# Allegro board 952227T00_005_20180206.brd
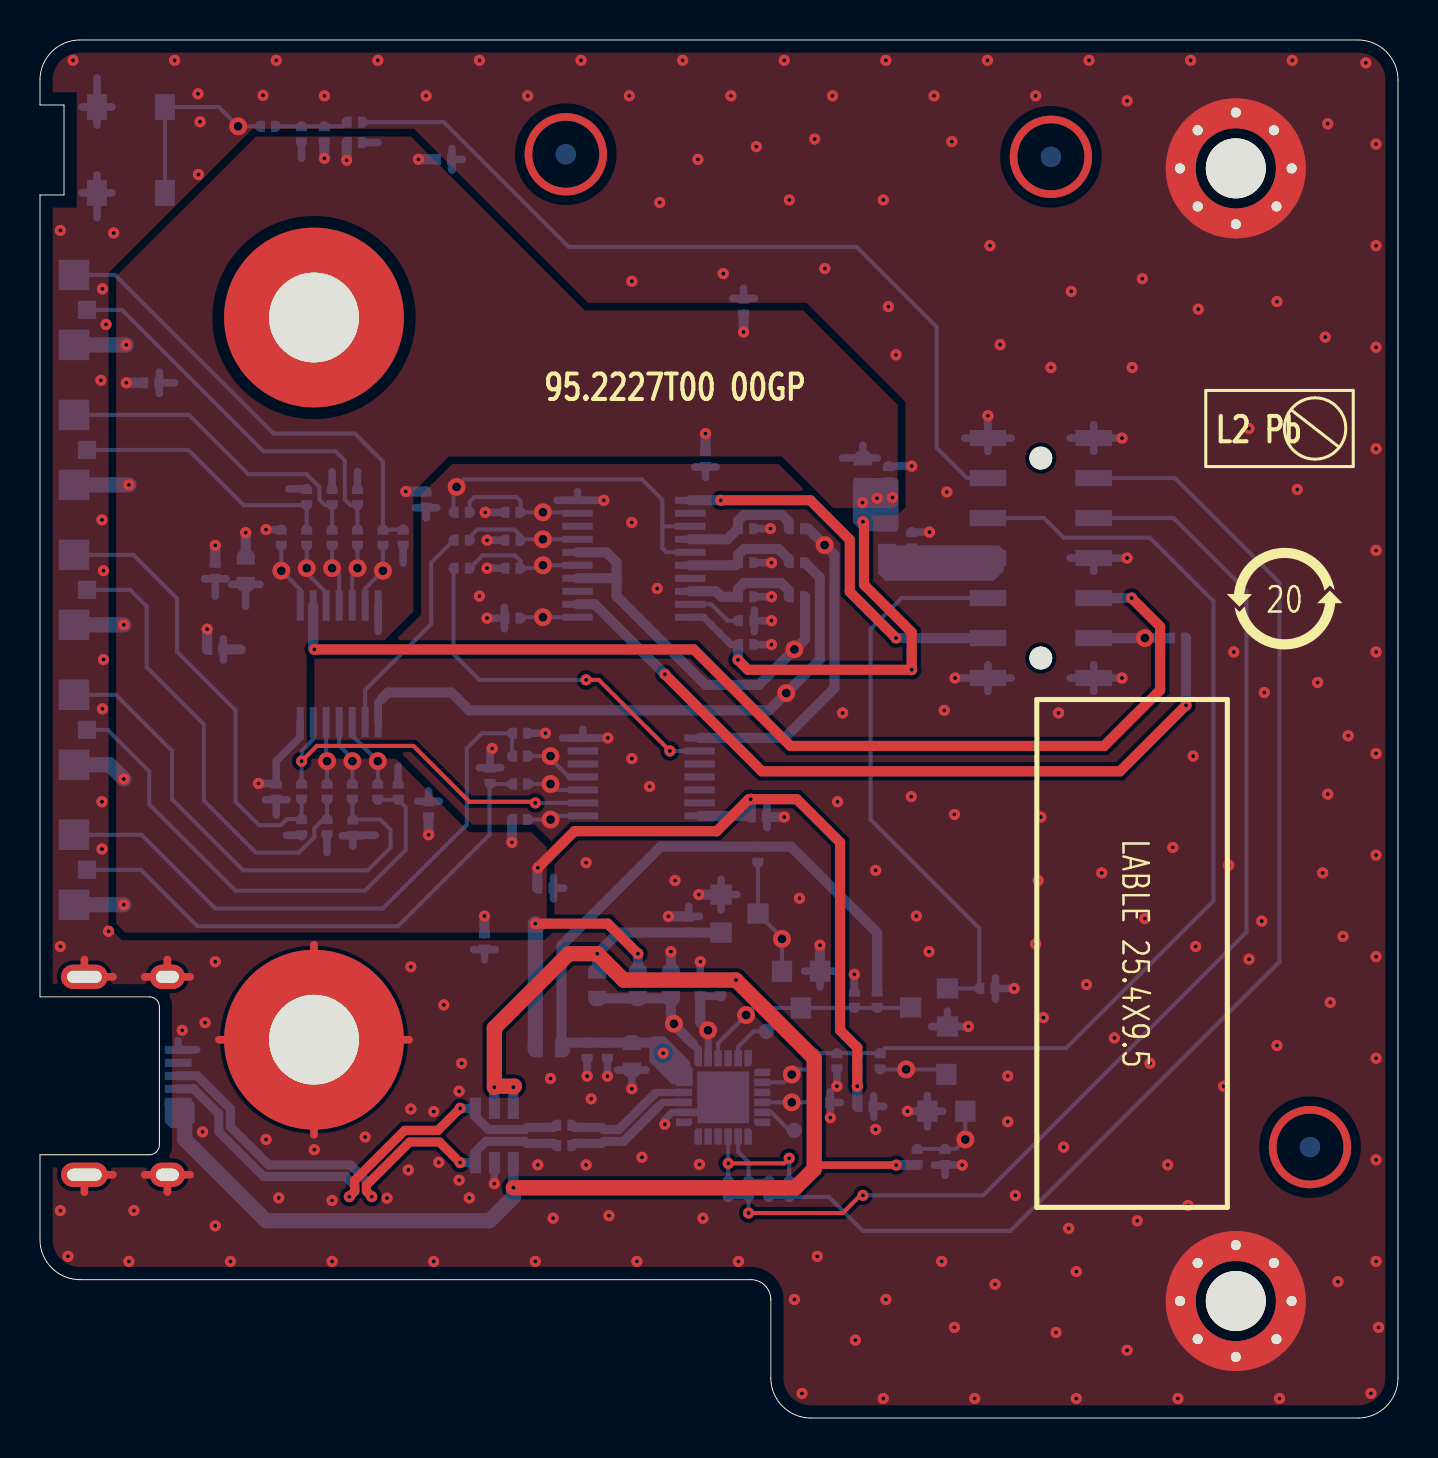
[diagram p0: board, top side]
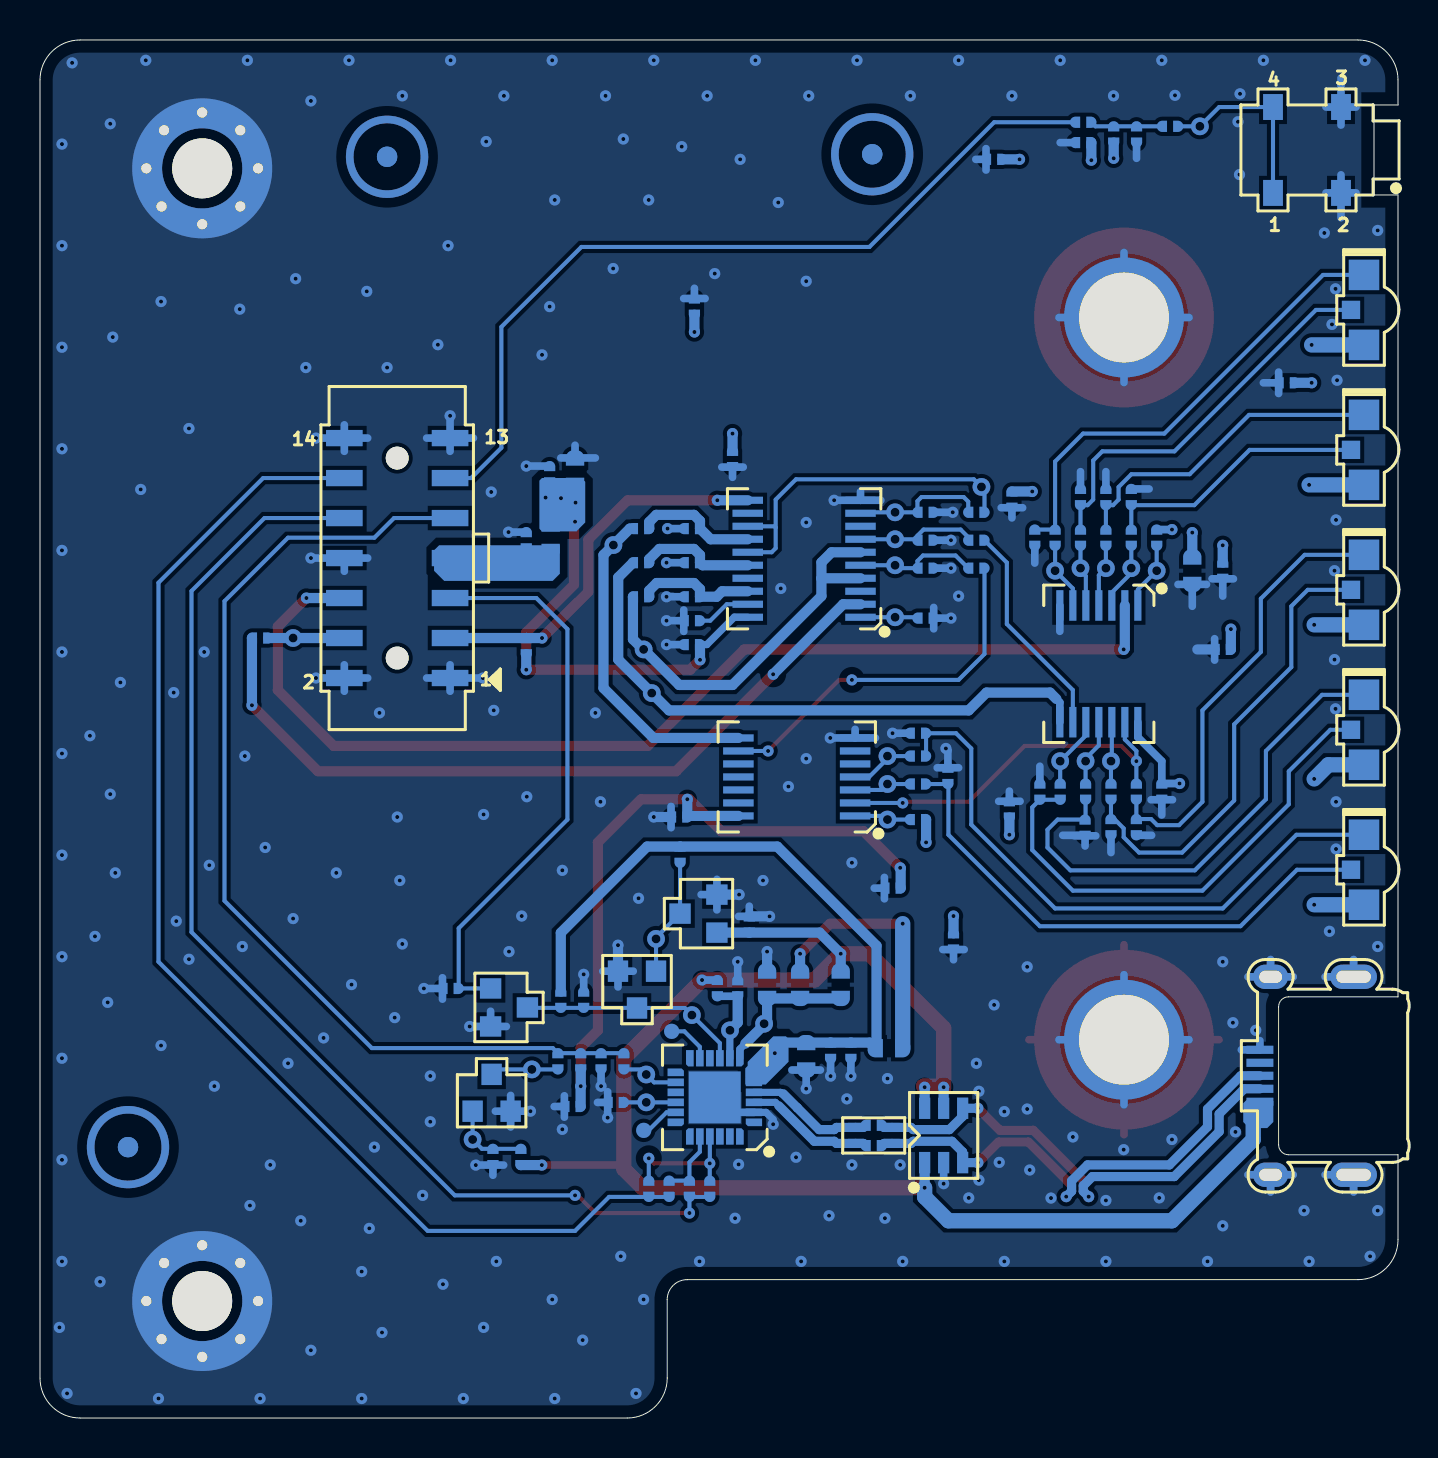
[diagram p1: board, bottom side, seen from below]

Outline 67.9 x 68.92 mm; copper layers: TOP, BOTTOM. Coordinates in mm from the lower left corner of the outline.
Outline path: 0,66.92 0,65.67 1.2,65.67 1.2,61.17 0,61.17 0,21.07 5.47,21.07 arc(5.82,20.92) 5.97,20.57 5.97,13.67 arc(5.82,13.31) 5.47,13.17 0,13.17 0,8.92 arc(0.59,7.51) 2,6.92 35.54,6.92 arc(36.25,6.63) 36.54,5.92 36.54,2 arc(37.13,0.59) 38.54,0 65.9,0 arc(67.31,0.59) 67.9,2 67.9,66.92 arc(67.31,68.33) 65.9,68.92 2,68.92 arc(0.59,68.33) 0,66.92

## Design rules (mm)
net group USB_DN: nets USB_DN USB_UART_DN
net group USB_DP: nets USB_DP USB_UART_DP
net group W 20MIL: nets LED_CLK0_1 LED_CLK0_1# LED_CLK0_1#_R LED_CLK0_1_R LED_CLK0_2 LED_CLK0_2_R LED_SYS_STAT_CLR_N LED_SYS_STAT_SCL LED_SYS_STAT_SDA

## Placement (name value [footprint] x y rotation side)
C1  100nF  [C-0402S0]  43.59 43.9 180 bottom
C2  100nF  [C-0402S0]  23.62 42.5 270 bottom
C3  100nF  [C-0402S0]  23.62 43.9 270 bottom
C4  100nF  [C-0402S0]  23.62 45.3 270 bottom
C5  100nF  [C-0402S0]  33.27 47.97 0 bottom
C7  100nF  [C-0402S0]  35.31 44.48 90 bottom
C8  100nF  [C-0402S0]  35.31 42.78 90 bottom
C9  100nF  [C-0402S0]  35.31 41.07 90 bottom
C10  100nF  [C-0402S0]  35.94 30.06 270 bottom
C11  10uF  [C-0603S0]  10.29 42.38 0 bottom
C12  100nF  [C-0402S0]  11.81 31.33 180 bottom
C14  4.7uF  [C-0402S0]  28.37 18.37 0 bottom
C15  100nF  [C-0402S0]  27.36 18.37 0 bottom
C17  4.7uF  [C-0402S0]  39.11 15.78 90 bottom
C18  10uF  [C-0603S0]  41.15 47.33 180 bottom
C20  100nF  [C-0402S0]  25.27 26.5 90 bottom
C21  100nF  [C-0402S0]  35.31 38.68 90 bottom
C22  100nF  [C-0402S0]  8.76 38.44 90 bottom
C23  100nF  [C-0402S0]  42.42 47.2 180 bottom
C24  100nF  [C-0402S0]  15.74 63.79 90 bottom
C27  100nF  [C-0402S0]  15.88 46.06 180 bottom
C29  100nF  [C-0402S0]  22.5 32.12 180 bottom
C30  100nF  [C-0402S0]  18.16 44.03 0 bottom
C32  100nF  [C-0402S0]  24 34.25 90 bottom
C33  100nF  [C-0402S0]  17.91 31.33 180 bottom
C36  100nF  [C-0402S0]  15.65 29.52 0 bottom
C39  100nF  [C-0402S0]  20.19 62.95 90 bottom
C41  100nF  [C-0402S0]  13.34 46.06 180 bottom
C44  100nF  [C-0402S0]  14.61 46.06 180 bottom
C46  100nF  [C-0402S0]  19.43 30.44 180 bottom
C47  100nF  [C-0402S0]  41.27 15.58 90 bottom
C48  100nF  [C-0402S0]  14.35 29.55 0 bottom
C49  100nF  [C-0402S0]  39.85 17.84 0 bottom
C50  100nF  [C-0402S0]  13.08 29.55 0 bottom
C56  1UF  [C-0402S0]  45.25 13.06 180 bottom
C57  100nF  [C-0402S0]  40.72 20.92 0 bottom
C58  10uF  [C-0603S0]  31.55 21.67 180 bottom
C59  1UF  [C-0402S0]  5.56 51.78 270 bottom
C60  1UF  [C-0402S0]  35.18 55.59 0 bottom
C61  1UF  [C-0402S0]  22.23 23.84 180 bottom
C62  1UF  [C-0402S0]  19.3 45.93 180 bottom
C63  1UF  [C-0402S0]  8.76 42.38 180 bottom
C147  1uF  [C-0402S0]  13.07 64.2 0 bottom
D19  AZ1355-04S.R7G  [SOT-23-6H1_25]  22.72 14.13 270 bottom
H1  Hole-4.5mm  [MPTH177R354B236-SMD]  13.7 18.92 0 top
H2  Hole-4.5mm  [MPTH177R354B236-SMD]  13.7 55.04 0 top
H3  Hole-3.0mm  [GMTH118R276]  59.79 62.5 0 top
H4  Hole-3.0mm  [GMTH118R276]  59.79 5.85 0 top
J1  HS5507F-R  [CN-S7X2-2HDS1]  50.04 43.01 180 bottom
J2  SUA-560MEB-L2S-TR  [CJ-USB-1X1-5C]  3.52 17.12 90 bottom
L1  90ohm  [L-2X1_2-4B]  26.21 14.13 0 bottom
LD1  LTST-S326KGJSKT  [LD-12-22H1S1]  1.7 55.42 0 bottom
LD2  LTST-S326KGJSKT  [LD-12-22H1S1]  1.7 48.42 0 bottom
LD3  LTST-S326KGJSKT  [LD-12-22H1S1]  1.7 41.42 0 bottom
LD4  LTST-S326KGJSKT  [LD-12-22H1S1]  1.7 34.42 0 bottom
LD5  LTST-S326KGJSKT  [LD-12-22H1S1]  1.7 27.42 0 bottom
NOREF  -  []  2 6.92 0 top
NOREF#2  -  []  0 61.17 0 top
NOREF#3  -  []  2 6.92 0 top
NOREF#4  -  []  58.04 47.58 0 top
NOREF#5  -  []  2 6.92 0 top
NOREF#6  -  []  64.9 149.69 0 top
NOREF#7  -  []  70.23 148.04 0 top
NOREF#8  -  []  58.42 150.07 0 top
NOREF#9  -  []  59.79 62.5 0 top
NOREF#10  -  []  62.23 40.98 0 top
NOREF#11  -  []  65.58 0 90 top
NOREF#12  -  [unnamed#2]  26.29 63.21 0 bottom
NOREF#13  -  [unnamed#2]  50.55 63.08 0 bottom
NOREF#14  -  [unnamed#2]  63.5 13.55 0 bottom
Q1  2N7002  [SOT-23BH1_11]  34.98 25.23 180 bottom
Q2  2N7002  [SOT-23BH1_11]  38.05 21.43 90 bottom
Q3  2N7002  [SOT-23BH1_11]  45.32 16.27 270 bottom
Q4  2N7002  [SOT-23BH1_11]  44.45 20.53 0 bottom
R1  33ohm  [R-0402S0]  37.85 41.07 90 bottom
R2  33ohm  [R-0402S0]  37.85 42.78 90 bottom
R3  33ohm  [R-0402S0]  37.85 44.48 90 bottom
R4  10Kohm  [R-0402S0]  43.59 38.6 180 bottom
R5  33ohm  [R-0402S0]  21.08 45.3 270 bottom
R6  33ohm  [R-0402S0]  21.08 43.9 270 bottom
R7  33ohm  [R-0402S0]  21.08 42.5 270 bottom
R8  33ohm  [R-0402S0]  56.9 39.01 90 bottom
R9  10Kohm  [R-0402S0]  23.62 40 90 bottom
R10  10Kohm  [R-0402S0]  35.31 39.88 270 bottom
R11  0  [R-0402S0]  35.43 11.47 180 bottom
R12  150ohm  [R-0402S0]  13.34 44.03 180 bottom
R13  10Kohm  [R-0402S0]  12.06 44.03 180 bottom
R14  150ohm  [R-0402S0]  14.61 44.03 180 bottom
R15  0  [R-0402S0]  37.46 11.47 180 bottom
R16  150ohm  [R-0402S0]  15.88 44.03 180 bottom
R18  150ohm  [R-0402S0]  17.14 44.03 180 bottom
R19  150ohm  [R-0402S0]  16.89 31.33 0 bottom
R20  150ohm  [R-0402S0]  15.62 31.33 0 bottom
R21  150ohm  [R-0402S0]  14.35 31.33 0 bottom
R22  150ohm  [R-0402S0]  13.08 31.33 0 bottom
R23  150ohm  [R-0402S0]  24 31.71 270 bottom
R24  10Kohm  [R-0402S0]  24 29.93 270 bottom
R25  150ohm  [R-0402S0]  24 33.11 270 bottom
R32  0  [R-0402S0]  26.21 14.64 90 bottom
R33  0  [R-0402S0]  26.21 13.62 90 bottom
R34  0  [R-0402S0]  34.41 11.47 180 bottom
R35  0  [R-0402S0]  36.44 11.47 180 bottom
R46  0ohm  [R-0603S0]  42.37 44.03 180 bottom
R47  4.7K  [R-0402S0]  14.22 64.2 180 bottom
R48  33  [R-0402S0]  15.74 64.81 90 bottom
R49  10ohm  [R-0402S0]  11.4 64.6 270 bottom
R50  150ohm  [R-0603S0]  29.59 18.09 180 bottom
R55  33ohm  [R-0402S0]  38.7 17.84 180 bottom
R61  10Kohm  [R-0402S0]  32.44 24.68 180 bottom
R62  10Kohm  [R-0402S0]  43.86 13.06 180 bottom
R63  10Kohm  [R-0402S0]  40.86 17.84 180 bottom
R64  33ohm  [R-0402S0]  42.01 17.84 180 bottom
R65  10Kohm  [R-0402S0]  35.9 28.17 0 bottom
R66  10Kohm  [R-0402S0]  41.86 20.92 0 bottom
R67  0ohm  [R-0603S0]  27.86 21.67 0 bottom
R68  0ohm  [R-0603S0]  29.9 21.67 0 bottom
R69  0ohm  [R-0603S0]  25.45 18.5 90 bottom
R72  4.7K  [R-0402S0]  34.03 21.5 0 bottom
R73  10Kohm  [R-0402S0]  33.01 21.5 180 bottom
R74  10Kohm  [R-0402S0]  47.37 21.48 270 bottom
SW1  EVQ-PSG02K  [SW-EVQ-PSG02K]  4.55 63.42 180 bottom
TP1  TP  [ICT]  37.71 14.39 0 bottom
TP2  TP  [ICT]  36.32 19.34 0 bottom
U1  SN74LVC2244APWR  [SSOP-20]  29.69 42.97 180 bottom
U2  MC74HC164ADTR2G  [SSOP-14S0]  14.96 37.72 90 bottom
U3  CP2102N-A01-GQFN24  [TQFN-4X4-24SH-H0_8S5]  34.16 16.04 90 bottom
U4  MC74HC164ADTR2G  [SSOP-14S0]  30.06 32.06 180 bottom

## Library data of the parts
C1-C5 C7-C10 C12 C15 C20-C24 C27 C29 C30 C32 C33 C36 C39 C41 C44 C46-C50 C57 C147 = CAP
C11 C14 C17 C18 C58 = M-CAP
C56 C59-C63 = CAP_6
D19 = SRV05
H1 H2 = TOOLING HOLE-1PIN-MPTH
H3 H4 = Hole-MTG-8VIA_3
J1 = CON7X2
J2 = USB-5-6G-A_0
L1 = CHOKE-4
LD1-LD5 = LED-1 GYP_0
Q1-Q4 = NFET-3P-GSD
R1-R10 R12-R14 R16 R18-R25 R55 R61-R66 R73 R74 = RES
R11 R15 R34 R35 R47-R50 R72 = RES_0
R32 R33 = RES_0: signal model: RES_0_R-0402S0_0_0
R46 R67-R69 = M-RES
SW1 = SW-EVQ-PSG02K_1
TP1 TP2 = TP
U1 = 74AHCT244_1
U2 U4 = SN74HC164PWT
U3 = CP2102N-A01-GQFN24R_4

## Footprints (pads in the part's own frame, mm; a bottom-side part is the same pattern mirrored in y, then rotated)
C-0402S0
  custom 0.127x0.127 smd: 1(0,-0.406) 2(0,0.406)
C-0603S0
  custom 0.191x0.191 smd: 1(0,-0.686) 2(0,0.686)
CJ-USB-1X1-5C
  rect 0.406x1.346 smd: 1(-1.3,3.385) 2(-0.65,3.385) 3(0,3.385) 4(0.65,3.385) 5(1.3,3.385)
  oval 1.219x1.753 hole 0.61x1.143: S1(-4.95,2.85) S2(4.95,2.85)
  oval 1.219x2.337 hole 0.61x1.727: S3(-4.95,-1.3) S4(4.95,-1.3)
CN-S7X2-2HDS1
  round 1.143 hole 1.143 unplated: (0,-5) (0,5)
  rect 1.829x0.813 smd: 1(2.644,-6) 2(-2.644,-6) 3(2.644,-4) 4(-2.644,-4) 5(2.644,-2) 6(-2.644,-2) 7(2.644,0) 8(-2.644,0) 9(2.644,2) 10(-2.644,2) 11(2.644,4) 12(-2.644,4) 13(2.644,6) 14(-2.644,6)
GMTH118R276
  round 2.997 hole 2.997 unplated: (0,0)
  round 0.813 hole 0.508: 1(0,2.794) 2(1.905,1.905) 3(2.794,0) 4(2.032,-1.905) 5(0,-2.794) 6(-1.905,-1.905) 7(-2.794,0) 8(-1.905,1.905)
ICT
  round 0.762 smd: 1(0,0)
L-2X1_2-4B
  rect 0.762x0.457 smd: 1(0.914,-0.4) 2(0.914,0.4) 3(-0.914,0.4) 4(-0.914,-0.4)
LD-12-22H1S1
  rect 0.914x0.914 smd: 1(0.65,0)
  rect 1.524x1.524 smd: 2(0,1.75) 3(0,-1.75)
MPTH177R354B236-SMD
  round 8.992 hole 4.496: 1(0,0)
R-0402S0
  custom 0.127x0.127 smd: 1(0,-0.406) 2(0,0.406)
R-0603S0
  custom 0.191x0.191 smd: 1(0,-0.686) 2(0,0.686)
SOT-23-6H1_25
  rect 1.067x0.559 smd: 1(1.359,-0.95) 2(1.359,0) 3(1.359,0.95) 4(-1.359,0.95) 5(-1.359,0) 6(-1.359,-0.95)
SOT-23BH1_11
  rect 1.067x1.016 smd: 1(0.92,-0.951) 2(0.92,0.951) 3(-0.921,0)
SSOP-14S0
  rect 1.524x0.356 smd: 1(2.918,-1.95) 2(2.918,-1.3) 3(2.918,-0.65) 4(2.918,0) 5(2.918,0.65) 6(2.918,1.3) 7(2.918,1.95) 8(-2.918,1.95) 9(-2.918,1.3) 10(-2.918,0.65) 11(-2.918,0) 12(-2.918,-0.65) 13(-2.918,-1.3) 14(-2.918,-1.95)
SSOP-20
  rect 1.524x0.356 smd: 1(2.819,-2.925) 2(2.819,-2.275) 3(2.819,-1.625) 4(2.819,-0.975) 5(2.819,-0.325) 6(2.819,0.325) 7(2.819,0.975) 8(2.819,1.625) 9(2.819,2.275) 10(2.819,2.925) 11(-2.819,2.925) 12(-2.819,2.275) 13(-2.819,1.625) 14(-2.819,0.975) 15(-2.819,0.325) 16(-2.819,-0.325) 17(-2.819,-0.975) 18(-2.819,-1.625) 19(-2.819,-2.275) 20(-2.819,-2.925)
SW-EVQ-PSG02K
  rect 0.991x1.295 smd: 1(-1.7,-2.147) 2(1.7,-2.147) 3(1.7,2.147) 4(-1.7,2.147)
TQFN-4X4-24SH-H0_8S5
  custom 0.095x0.095 smd: 1(-1.25,-1.956) 6(1.25,-1.956) 7(1.956,-1.25) 12(1.956,1.25) 13(1.25,1.956) 18(-1.25,1.956) 19(-1.956,1.25) 24(-1.956,-1.25)
  rect 0.381x0.813 smd: 2(-0.75,-1.956) 3(-0.25,-1.956) 4(0.25,-1.956) 5(0.75,-1.956) 14(0.75,1.956) 15(0.25,1.956) 16(-0.25,1.956) 17(-0.75,1.956)
  rect 0.813x0.381 smd: 8(1.956,-0.75) 9(1.956,-0.25) 10(1.956,0.25) 11(1.956,0.75) 20(-1.956,0.75) 21(-1.956,0.25) 22(-1.956,-0.25) 23(-1.956,-0.75)
  rect 2.591x2.591 smd: 25(0,0)
unnamed#2
  round 1.016 smd: (0,0) (0,0)

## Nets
GND: C1.2 C2.2 C3.2 C4.2 C5.2 C7.2 C8.2 C9.2 C10.1 C11.2 C12.1 C14.2 C15.2 C17.2 C18.2 C20.2 C21.2 C22.2 C23.2 C24.2 C27.2 C29.2 C30.2 C32.2 C33.2 C36.2 C39.2 C41.2 C44.2 C46.2 C47.2 C48.2 C49.2 C50.2 C56.1 C57.1 C58.2 C59.1 C60.1 C61.1 C62.1 C63.1 C147.2 D19.2(GND) H1.1 H2.1 H3.1(GND1) H3.2(GND2) H3.3(GND3) H3.4(GND4) H3.5(GND5) H3.6(GND6) H3.7(GND7) H3.8(GND8) H4.1(GND1) H4.2(GND2) H4.3(GND3) H4.4(GND4) H4.5(GND5) H4.6(GND6) H4.7(GND7) H4.8(GND8) J1.1 J1.2 J1.8 J1.13 J1.14 J2.5(GND) J2.S1(G1) J2.S2(G2) J2.S3(G3) J2.S4(G4) Q1.2(S) Q2.2(S) Q3.2(S) Q4.2(S) R9.1 R10.1 R50.1 R61.2 R73.2 R74.1 SW1.2(/B) SW1.3(B) U1.10(GND) U2.7(GND) U3.2(GND) U3.25(THERMAL) U4.7(GND)
P3V3: C5.1 C10.2 C11.1 C12.2 C18.1 C20.1 C21.1 C22.1 C23.1 C24.1 C39.1 C46.1 C47.1 C59.2 C60.2 C61.2 C62.2 C63.2 LD1.2(A) LD2.2(A) LD3.2(A) LD4.2(A) LD5.2(A) R4.1 R13.2 R24.2 R46.2 R47.1 R63.1 R68.1 R69.1 U1.20(VCC) U2.14(VCC) U4.14(VCC)
P3V3_CP2104: C14.1 C15.1 R50.2 R65.1 R66.1 R69.2 U3.5(VIO) U3.6(VDD)
P3V3_IN: C1.1 J1.7 R46.1
P5V: D19.1(I/O1) D19.5(VCC) D19.6(I/O2) J2.1(VBUS) Q1.1(G) R61.1 R62.1 R67.1 R72.1
P5V_CP2104: C58.1 R67.2 R68.2 U3.7(VREGIN)
74LCX244_JTAG_2_1G: R9.2 U1.1(1G)
74LCX244_JTAG_2_2G: R10.2 U1.19(2G)
CP2104_VBUS: R72.2 R73.1 U3.8(VBUS)
FP_BTN_N: C147.1 R47.2 R48.1 R49.1
LED_CLK0_1: R2.2 U2.8(CLK)
LED_CLK0_1#: R1.2 U1.4(1A2) U1.6(1A3)
LED_CLK0_1#_R: C9.1 R1.1 U1.18(1Y1)
LED_CLK0_1_R: C8.1 R2.1 U1.16(1Y2)
LED_CLK0_2: R3.2 U4.8(CLK)
LED_CLK0_2_R: C7.1 R3.1 U1.14(1Y3)
LED_CLR0#_1: R6.2 U2.9(CLR#)
LED_CLR0#_1_R: C3.1 R6.1 U1.7(2Y2)
LED_CLR0#_2: R7.2 U4.9(CLR#)
LED_CLR0#_2_R: C2.1 R7.1 U1.5(2Y3)
LED_CLR0_1#: R5.2 U1.13(2A2) U1.15(2A3)
LED_CLR0_1#_R: C4.1 R5.1 U1.9(2Y1)
LED_FAN_STATUS_GRN: C33.1 LD4.1(C2) R19.2
LED_FAN_STATUS_GRN_R: R19.1 U2.10(QE)
LED_FAN_STATUS_YEL: C36.1 LD4.3(C1) R20.2
LED_FAN_STATUS_YEL_R: R20.1 U2.11(QF)
LED_GNSS_STATUS_GRN: C27.1 LD1.1(C2) R16.2
LED_GNSS_STATUS_GRN_R: R16.1 U2.5(QC)
LED_GNSS_STATUS_YEL: C30.1 LD1.3(C1) R18.2
LED_GNSS_STATUS_YEL_R: R18.1 U2.6(QD)
LED_MOD_PRSNT: C56.2 Q3.1(G) R62.2
LED_MOD_PRSNT_N: Q3.3(D) R64.1
LED_PWR_STATUS_GRN: C29.1 LD5.1(C2) R23.2
LED_PWR_STATUS_GRN_R: R23.1 U4.3(QA)
LED_PWR_STATUS_YEL: C32.1 LD5.3(C1) R25.2
LED_PWR_STATUS_YEL_R: R25.1 U4.4(QB)
LED_SYNC_STATUS_GRN: C41.1 LD2.1(C2) R12.2
LED_SYNC_STATUS_GRN_R: R12.1 U2.3(QA)
LED_SYNC_STATUS_YEL: C44.1 LD2.3(C1) R14.2
LED_SYNC_STATUS_YEL_R: R14.1 U2.4(QB)
LED_SYS_STAT_CLR_N: J1.3 R4.2 U1.11(2A1)
LED_SYS_STAT_SCL: R8.2 U1.2(1A1)
LED_SYS_STAT_SCL_R: J1.4 R8.1
LED_SYS_STAT_SDA: J1.6 U2.2(B)
LED_SYS_STAT_SDA_PU0: R13.1 U2.1(A)
LED_SYS_STAT_SDA_PU1: R24.1 U4.1(A)
LED_SYS_STATUS_GRN: C48.1 LD3.1(C2) R21.2
LED_SYS_STATUS_GRN_R: R21.1 U2.12(QG)
LED_SYS_STATUS_YEL: C50.1 LD3.3(C1) R22.2
LED_SYS_STATUS_YEL_R: R22.1 U2.13(QH) U4.2(B)
MOD_BTN_N: J1.11 R48.2
RST_CP2104: Q1.3(D) Q2.1(G) R65.2
RST_CP2104_N: C57.2 Q2.3(D) Q4.3(D) R66.2 U3.9(RSTB)
RST_SW_BTN_EN_N: R49.2 SW1.1(/A) SW1.4(A)
RST_SW_TO_CP2104: J1.5 Q4.1(G) R74.2
UART_CP2104_RXD: R11.2 R35.2 U3.20(RXD)
UART_CP2104_TXD: R15.2 R34.2 U3.21(TXD)
USB_CONS_PRSNT_GPIO_N: R55.1 U3.14(GPIO.0/TXT)
USB_CONS_PRSNT_N: C49.1 J1.9 R55.2 R63.2 R64.2
USB_DN: D19.4(I/O4) J2.2(D-) L1.4 R32.1
USB_DP: D19.3(I/O3) J2.3(D+) L1.3 R33.1
USB_UART0_RXD: J1.12 R15.1 R35.1
USB_UART0_TXD: J1.10 R11.1 R34.1
USB_UART_DN: L1.1 R32.2 U3.4(D-)
USB_UART_DP: L1.2 R33.2 U3.3(D+)
N292646: C17.1 U3.16(NC2)
N535645: TP1.1 U3.17(SUSPEND)
N535677: TP2.1 U3.11(GPIO.3/WAKEUP)

Pads without a net: J2 4; U1 3 8 12 17; U3 1 10 12 13 15 18 19 22 23 24; U4 5 6 10 11 12 13

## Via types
v1: diameter 0.889, hole 0.445, TOP to BOTTOM, 29 vias
v2: diameter 0.559, hole 0.203, TOP to BOTTOM, 281 vias

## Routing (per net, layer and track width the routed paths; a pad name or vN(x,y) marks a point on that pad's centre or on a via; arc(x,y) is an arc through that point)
GND: length 187.1
  TOP w0.381: 2.22,11.3 J2.S3 3.64,12.17 ; H1.1 13.7,23.67 ; H1.1 18.45,18.92 ; H1.1 13.7,14.17 ; H1.1 8.95,18.92 ; 3.64,22.07 J2.S4 2.22,22.93 ; J2.S2 7.5,22.07 ; J2.S2 5.24,22.07 ; J2.S2 6.37,22.93 ; 5.24,12.17 J2.S1 ; J2.S1 7.5,12.17 ; J2.S1 6.37,11.3
  BOTTOM w0.356: U3.2 31.6,15.29 31.24,14.93 v2(31.24,14.69)
  BOTTOM w0.381: 36.35,29.52 C10.1 36.35,30.59 ; 28.88,17.4 R50.1 ; R50.1 v2(29.59,16.47) ; R50.1 30.3,17.4 ; 25.86,45.9 U1.10 ; U1.10 26.87,46.33 ; U1.10 v2(28.19,45.9) ; C56.1 v2(46.11,12.65) ; C56.1 44.72,12.65 ; C56.1 45.25,12.14 ; J1.13 48.57,49.01 ; J1.13 v2(47.4,50.12) ; J1.13 47.4,48.35 ; J1.13 46.23,49.01 ; v2(22.61,33.49) 22.5,33.39 C29.2 ; Q3.2 44.37,16.13 ; Q3.2 45.13,15.35 ; Q3.2 44.37,14.56 ; Q3.2 v2(43.38,15.35) ; R10.1 35.71,40.41 ; R10.1 35.71,39.34 ; R10.1 v2(36.58,39.88) ; 32.97,25.09 R61.2 32.44,25.6 ; C39.2 20.6,63.49 ; C39.2 21.11,62.95 ; C39.2 20.6,62.42 ; C8.2 v2(36.58,42.78) ; C14.2 v2(28.37,17.1) ; 10.45,55.04 H2.1 ; H2.1 13.7,58.29 ; H2.1 16.95,55.04 ; H2.1 13.7,51.79 ; J1.8 v2(54.35,43.01) ; J1.8 51.52,43.01 ; J1.8 52.68,42.35 ; C36.2 15.67,29.14 16.76,29.14 ; C36.2 15.65,28.61 ; C36.2 15.11,29.12 ; C36.2 16.18,29.12 ; R9.1 v2(22.35,40) ; R9.1 23.22,40.54 ; R9.1 23.22,39.47 ; C60.1 35.71,55.99 ; C60.1 35.18,56.5 ; C60.1 34.64,55.99 ; C48.2 14.35,28.28 ; C18.2 41.15,48.65 ; C18.2 41.86,48.02 ; C18.2 40.13,48.02 ; C47.2 42.19,15.58 ; C47.2 41.68,15.04 ; C47.2 41.68,16.12 ; J1.1 48.57,37.01 ; J1.1 47.4,37.67 ; J1.1 47.4,36.35 ; J1.1 v2(45.75,37.01) ; C3.2 v2(22.35,43.9) ; 18.9,30.85 C46.2 ; C46.2 19.97,30.85 ; C46.2 19.43,31.35 ; C63.1 9.3,41.97 ; C63.1 8.76,41.11 ; C63.1 8.23,41.97 ; C7.2 v2(36.52,44.48) ; 6.91,18.87 J2.5 7.83,18.42 ; C27.2 15.88,47.33 ; 34.06,25.42 Q1.2 ; Q1.2 34.06,26.94 ; Q1.2 34.84,26.18 ; C41.2 12.45,46.47 ; 21.97,32.52 C29.2 ; C29.2 23.04,32.52 ; J2.S1 7.5,12.17 ; J2.S1 5.24,12.17 ; J2.S1 6.37,11.3 ; U4.7 27.14,34.44 ; U4.7 26.13,34.01 ; U4.7 v2(28.39,34.01) ; 33.27,47.05 C5.2 ; C5.2 32.74,47.56 ; C5.2 33.81,47.56 ; 21.69,23.43 C61.1 ; C61.1 22.76,23.43 ; C61.1 22.23,22.92 ; C17.2 39.52,16.32 ; C17.2 v2(39.52,15.02) ; C17.2 40.03,15.78 ; C33.2 17.91,32.6 ; C44.2 14.61,47.33 ; 11.28,30.92 C12.1 ; C12.1 11.81,30.16 ; C12.1 12.35,30.92 ; C1.2 v2(44.48,44.31) ; C20.2 25.68,27.04 ; C20.2 26.19,26.5 ; C20.2 25.68,25.97 ; J2.S2 6.37,22.93 ; J2.S2 5.24,22.07 ; J2.S2 7.5,22.07 ; 3.64,12.17 J2.S3 2.22,11.3 ; Q2.2 39.76,22.35 ; Q2.2 38.24,22.35 ; Q2.2 39,21.56 ; 51.52,49.01 J1.14 ; J1.14 52.68,49.67 ; J1.14 v2(54.1,49.01) ; J1.14 52.68,48.35 ; H1.1 13.7,22.17 ; H1.1 13.7,15.67 ; H1.1 16.95,18.92 ; H1.1 10.45,18.92 ; R73.2 v2(33.01,22.82) ; 18.77,45.53 C62.1 ; C62.1 19.84,45.53 ; C62.1 19.3,45.02 ; C24.2 16.89,63.79 ; 52.68,36.35 J1.2 ; J1.2 v2(54.1,37.01) ; J1.2 52.68,37.67 ; J1.2 51.52,37.01 ; C59.1 5.97,52.31 ; C59.1 6.73,51.78 ; C59.1 5.97,51.24 ; SW1.2 2.85,60.03 ; SW1.2 3.6,61.27 ; SW1.2 2.1,61.27 ; SW1.2 2.85,62.17 ; SW1.3 3.6,65.57 ; SW1.3 2.85,64.67 ; SW1.3 2.85,67.02 ; SW1.3 2.1,65.57 ; Q4.2 45.37,20.34 ; Q4.2 44.58,19.58 ; Q4.2 v2(46.42,19.58) ; C147.2 13.07,63 ; 47.78,20.95 R74.1 ; R74.1 47.78,22.02 ; R74.1 v2(48.71,21.48) ; 9.17,37.9 C22.2 9.17,38.98 ; U3.2 33.41,15.29 U3.25 ; v2(25.27,34.25) C32.2 ; C15.2 v2(27.36,17.1) ; 12.32,29.14 C50.2 ; C21.2 v2(36.58,38.68) ; C11.2 10.29,40.6 ; C11.2 11,41.69 ; C11.2 9.58,41.69 ; 2.22,22.93 J2.S4 3.64,22.07 ; C57.1 v2(40.72,22.19) ; C4.2 v2(22.26,45.3) ; C2.2 v2(22.35,42.5) ; C9.2 v2(36.58,41.07) ; U2.7 16.91,39.35 ; D19.2 v2(22.72,11.72) ; C49.2 v2(39.85,16.6) ; C23.2 v2(43.59,47.61) ; C30.2 18.16,42.76
  BOTTOM w0.508: C58.2 v2(31.55,23.33) ; C10.1 v2(37.21,30.06) ; R61.2 v2(31.42,25.09) ; Q1.2 v2(32.94,26.18) ; C22.2 10.03,38.44 ; Q2.2 v2(39,23.65)
  vias: v2(1.02,59.4) v2(1.02,23.58) v2(1.02,10.37) v2(1.4,8.09) v2(1.65,67.9) v2(3.05,51.9) v2(3.12,56.47) v2(3.1,44.92) v2(3.12,35.47) v2(3.1,30.82) v2(3.1,28.46) v2(3.17,42.38) v2(3.17,37.93) v2(3.3,54.7) v2(3.43,24.34) v2(3.68,59.27) v2(4.45,7.83) v2(4.7,10.37) v2(6.73,67.9) v2(7.11,19.39) v2(7.9,66.23) v2(7.92,62.19) v2(8,64.83) v2(8.13,14.31) v2(8.26,19.77) v2(8.76,22.82) v2(8.76,9.61) v2(9.53,7.83) v2(11.15,66.15) v2(11.3,13.93) v2(11.81,67.9) v2(11.94,11.01) v2(13.72,13.42) v2(14.22,66.13) v2(14.61,10.88) v2(14.61,7.83) v2(16.26,14.06) v2(16.89,67.9) v2(17.35,11) v2(18.41,12.41) v2(18.54,22.57) v2(18.54,15.45) v2(19.3,66.13) v2(19.68,15.33) v2(19.68,7.83) v2(19.94,12.79) v2(20.19,20.66) v2(20.95,16.34) v2(20.95,11.9) v2(21.08,17.74) v2(21.46,11.01) v2(21.97,67.9) v2(21.97,41.11) v2(24.38,66.13) v2(24.77,7.83) v2(24.89,12.66) v2(25.53,16.98) v2(25.65,9.99) v2(27.05,67.9) v2(27.3,27.77) v2(27.3,12.66) v2(27.56,15.96) v2(28.45,10.12) v2(29.46,66.13) v2(29.59,56.86) v2(29.59,44.79) v2(29.59,32.98) v2(29.84,7.83) v2(30.1,13.04) v2(30.48,31.58) v2(30.86,41.49) v2(30.99,60.79) v2(31.75,26.88) v2(32.13,67.9) v2(32.89,62.95) v2(32.97,12.68) v2(33.15,9.99) v2(34.16,57.24) v2(34.54,66.13) v2(34.92,7.83) v2(35.81,63.59) v2(37.21,67.9) v2(37.47,60.92) v2(37.72,5.93) v2(37.97,25.99) v2(38.1,1.23) v2(38.73,63.97) v2(38.86,8.09) v2(39.24,57.49) v2(39.62,66.13) v2(39.88,30.82) v2(40.13,35.27) v2(40.77,3.9) v2(41.78,27.39) v2(41.78,14.44) v2(42.16,60.92) v2(42.16,0.98) v2(42.29,67.9) v2(42.29,5.93) v2(42.42,55.59) v2(42.8,53.17) v2(43.56,31.07) v2(43.81,25.11) v2(44.45,23.33) v2(44.7,66.13) v2(45.09,7.83) v2(45.21,35.39) v2(45.34,46.31) v2(45.59,63.84) v2(45.72,30.19) v2(45.72,4.53) v2(46.74,0.98) v2(47.37,67.9) v2(47.5,58.63) v2(47.75,6.69) v2(48.01,53.68) v2(48.39,17.1) v2(48.39,14.82) v2(48.77,11.14) v2(49.78,66.13) v2(49.78,23.71) v2(49.91,26.88) v2(50.04,30.06) v2(50.16,20.03) v2(50.55,52.54) v2(50.8,4.28) v2(50.93,35.27) v2(51.18,13.55) v2(51.44,9.48) v2(51.56,56.35) v2(51.82,7.33) v2(51.82,0.98) v2(52.32,21.68) v2(52.45,67.9) v2(53.09,27.26) v2(53.72,19.01) v2(54.36,65.87) v2(54.36,3.39) v2(54.61,52.54) v2(54.86,9.87) v2(55.12,56.98) v2(55.24,24.98) v2(55.5,17.74) v2(56.39,12.66) v2(56.64,28.53) v2(56.9,0.98) v2(57.4,10.63) v2(57.53,67.9) v2(57.66,33.11) v2(57.78,23.58) v2(57.91,55.46) v2(59.18,16.6) v2(59.44,27.65) v2(59.69,38.31) v2(60.45,49.49) v2(60.45,22.95) v2(61.09,24.85) v2(61.21,36.28) v2(61.85,55.84) v2(61.85,18.63) v2(61.98,0.98) v2(62.61,67.9) v2(62.87,46.44) v2(63.88,36.79) v2(64.14,27.26) v2(64.26,54.06) v2(64.39,64.73) v2(64.39,31.2) v2(64.52,20.79) v2(64.9,6.82) v2(65.15,24.09) v2(65.41,34.12) v2(66.29,67.78) v2(66.55,1.23) v2(66.8,63.71) v2(66.8,58.63) v2(66.8,53.55) v2(66.8,48.47) v2(66.8,43.39) v2(66.8,38.31) v2(66.8,33.23) v2(66.8,28.15) v2(66.8,23.07) v2(66.8,17.99) v2(66.8,12.91) v2(66.8,7.83) v2(66.93,4.53)
P3V3: length 101.4
  TOP w0.508: v2(29.9,23.22) 28.39,24.72 v2(24.77,24.72) ; v2(34.9,37.92) 35.39,37.42 v2(43.59,37.42) 43.59,39.29 41.2,41.68 41.2,44.78 v2(41.15,44.83) ; v2(40.86,16.6) 40.86,18.53 40.01,19.39 40.01,28.79 37.85,30.95 v2(35.53,30.95) 35.43,30.95 33.83,29.35 26.72,29.35 v2(24.89,27.52)
  BOTTOM w0.356: C21.1 34.56,38.68 33.19,40.05 U1.20
  BOTTOM w0.381: U2.14 13.01,34.05 11.81,32.85 C12.2 v2(10.92,31.73) ; R13.2 v2(11.3,44.43)
  BOTTOM w0.508: C21.1 v2(34.9,37.92) ; C47.1 40.87,16.59 v2(40.86,16.6) R63.1 ; C46.1 v2(19.43,29.17) ; R47.1 v2(14.22,63) ; C63.2 v2(8.76,43.65) ; R4.1 v2(43.59,37.42) ; C59.2 v2(4.32,51.78) ; U4.14 35.48,30.11 C10.2 v2(35.53,30.95) ; C61.2 v2(22.23,25.11) ; R24.2 v2(23.6,28.79) ; C62.2 v2(18.29,46.34) ; v2(24.89,27.52) 24.87,27.49 C20.1 ; C60.2 v2(35.18,54.32) ; C39.1 v2(18.92,62.95) ; C24.1 v2(15.33,62.91) ; C11.1 v2(10.29,44.28) ; C22.1 v2(8.36,39.46) ; C5.1 v2(33.27,49.24) ; R68.1 v2(29.9,23.22)
  BOTTOM w0.762: LD4.2 3.48,32.67 v2(4.19,31.96) ; LD3.2 v2(4.19,39.67) ; LD1.2 v2(4.32,53.67) ; R69.1 v2(24.77,24.72) ; LD2.2 v2(4.45,46.67) ; LD5.2 v2(4.19,25.67)
  vias: v2(41.12,45.78) v2(41.85,46) v2(42.62,46.03)
P3V3_CP2104: length 33.1
  BOTTOM w0.508: v2(31.16,18.25) 30.63,18.78 R50.2 C14.1 C15.1 26.42,18.78 R69.2 26.07,18.56 26.07,23.62 31.03,28.58 R65.1 37.55,28.58 41.86,24.27 R66.1
P5V: length 81.8
  TOP w0.381: 38.71,12.46 38.9,12.65 v2(42.81,12.65)
  TOP w0.762: v2(23.67,11.52) 37.77,11.52 38.71,12.46 38.71,17.99 v2(34.8,21.9) 29.18,21.9 v2(27.86,23.22) 26.44,23.22 22.72,19.5 v2(22.72,16.55) 22.77,16.6 23.72,16.6 v2(23.67,16.55)
  BOTTOM w0.381: R72.1 v2(34.8,21.9)
  BOTTOM w0.508: Q1.1 R61.1 28.92,24.28 v2(27.86,23.22) R67.1 ; D19.5 v2(22.72,16.55) ; D19.6 v2(23.67,16.55) ; D19.1 v2(23.67,11.52) ; R62.1 v2(42.81,12.65)
  BOTTOM w0.762: v2(23.67,11.52) 23.67,11.05 22.48,9.87 11.3,9.87 7.24,13.93 7.24,15.07
P5V_CP2104: length 7.2
  BOTTOM w0.356: U3.7 32.91,18.45 32.63,18.73
  BOTTOM w0.508: 32.63,18.73 31.69,19.67 v1(31.69,19.72) 31.55,19.87 C58.1 R68.2 R67.2
74LCX244_JTAG_2_1G: length 2.9
  BOTTOM w0.203: R9.2 24.07,40.05 v1(25.15,40.05) U1.1
74LCX244_JTAG_2_2G: length 2.7
  BOTTOM w0.203: U1.19 33.56,40.7 34.39,39.88 R10.2
CP2104_VBUS: length 4.3
  BOTTOM w0.356: U3.8 33.41,19.38 v1(33.4,19.39)
  BOTTOM w0.381: R72.2 R73.1
  BOTTOM w0.508: R73.1 33.01,19.78 v1(33.4,19.39)
FP_BTN_N: length 3.6
  BOTTOM w0.203: R49.1 C147.1 R47.2 15.13,64.6 R48.1
LED_CLK0_1: length 29.8
  BOTTOM w0.381: U2.8 16.91,35.79 17.08,35.96
  BOTTOM w0.508: 17.08,35.96 17.4,36.28 20.57,36.28 21.46,35.39 36.45,35.39 v1(37.31,36.26) 38.99,37.93 38.99,42.04 R2.2
LED_CLK0_1#: length 20.1
  BOTTOM w0.508: R1.2 38.25,38.95 37.74,38.44 v1(37.72,38.44) 35.94,36.66 33.27,36.66 28.83,41.11 28.83,42 ; 28.83,42 28.83,42 U1.4 ; 28.83,42 28.83,42.79 28.32,43.3 U1.6
LED_CLK0_1#_R: length 6
  BOTTOM w0.508: U1.18 33.79,41.35 34.07,41.07 C9.1 34.9,41.46 35.2,41.76 37.06,41.76 37.44,41.39 R1.1
LED_CLK0_1_R: length 5.9
  BOTTOM w0.508: U1.16 34.77,42.65 C8.1 34.9,43.16 35.2,43.47 36.93,43.47 37.44,42.96 R2.1
LED_CLK0_2: length 16.5
  BOTTOM w0.508: U4.8 37.23,34.01 39.73,36.51 39.73,43.16 v1(39.23,43.66) 38.41,44.48 R3.2
LED_CLK0_2_R: length 6.1
  BOTTOM w0.508: U1.14 34.37,43.95 C7.1 34.9,44.87 35.2,45.17 37.09,45.17 37.44,44.82 R3.1
LED_CLR0#_1: length 10.9
  BOTTOM w0.203: R6.2 19.56,42.78 19.56,39.71 16.26,36.41 U2.9
LED_CLR0#_1_R: length 6.1
  BOTTOM w0.203: R6.1 21.49,44.05 21.87,44.44 23.72,44.44 24.03,44.13 C3.1 24.08,43.95 v1(25.15,43.95) U1.7
LED_CLR0#_2: length 18.6
  TOP w0.203: v2(31.5,33.36) 27.94,36.92 v2(27.3,36.92)
  BOTTOM w0.203: v2(31.5,33.36) 31.5,33.36 U4.9 ; R7.2 20.68,38.21 21.97,36.92 v2(27.3,36.92)
LED_CLR0#_2_R: length 6.2
  BOTTOM w0.203: U1.5 v1(25.15,42.65) 25,42.5 C2.1 24.03,42.86 23.75,43.14 22.12,43.14 R7.1
LED_CLR0_1#: length 17.5
  BOTTOM w0.203: 31.11,44.54 31.11,45.93 30.1,46.95 21.21,46.95 v1(20.83,46.57) 20.68,46.42 R5.2 ; 31.11,44.54 31.11,43.5 31.32,43.3 U1.15 ; 31.11,44.54 31.18,44.6 U1.13
LED_CLR0_1#_R: length 6.7
  BOTTOM w0.203: R5.1 21.49,45.83 21.72,46.06 23.83,46.06 24.03,45.86 C4.1 v1(25.15,45.3) 26.83,45.3 U1.9
LED_FAN_STATUS_GRN: length 24.8
  BOTTOM w0.203: R19.2 C33.1 18.29,30.54 18.29,28.41 16.26,26.38 9.78,26.38 5.46,30.69 5.46,32.34 3.39,34.42 LD4.1
LED_FAN_STATUS_GRN_R: length 3.6
  BOTTOM w0.203: U2.10 15.61,34.13 v1(16.89,32.85) R19.1
LED_FAN_STATUS_YEL: length 25.3
  BOTTOM w0.203: R20.2 15.62,29.96 15.65,29.93 17.02,29.93 17.53,29.42 17.53,28.53 16.38,27.39 10.16,27.39 6.6,30.95 6.6,33.36 3.79,36.17 LD4.3
LED_FAN_STATUS_YEL_R: length 3.3
  BOTTOM w0.203: R20.1 v1(15.62,32.85) 15.62,32.98 14.96,33.64 U2.11
LED_GNSS_STATUS_GRN: length 19.9
  BOTTOM w0.203: R16.2 C27.1 15.52,45.65 15.24,45.93 15.24,47.89 14.78,48.35 11.18,48.35 4.1,55.42 LD1.1
LED_GNSS_STATUS_GRN_R: length 3.1
  BOTTOM w0.203: R16.1 v1(15.88,42.5) 15.88,42.38 15.61,42.11 U2.5
LED_GNSS_STATUS_YEL: length 23.7
  BOTTOM w0.203: LD1.3 3.75,57.17 11.68,49.24 15.75,49.24 17.14,47.84 R18.2 C30.1
LED_GNSS_STATUS_YEL_R: length 3.4
  BOTTOM w0.203: U2.6 16.26,41.49 v1(17.14,42.38) R18.1
LED_MOD_PRSNT: length 4
  BOTTOM w0.203: R62.2 C56.2 45.8,13.46 v1(46.27,13.93) Q3.1
LED_MOD_PRSNT_N: length 3.4
  BOTTOM w0.203: Q3.3 45.07,17.43 v1(43.31,17.43) R64.1
LED_PWR_STATUS_GRN: length 26.8
  BOTTOM w0.203: R23.2 C29.1 22.48,31.68 22.48,29.17 17.91,24.6 7.87,24.6 5.05,27.42 LD5.1
LED_PWR_STATUS_GRN_R: length 2.9
  BOTTOM w0.203: R23.1 v1(25.53,31.71) 25.82,31.41 U4.3
LED_PWR_STATUS_YEL: length 30.4
  BOTTOM w0.203: LD5.3 5.08,29.17 8.76,25.49 17.14,25.49 21.34,29.68 21.34,33.49 22.1,34.25 C32.1 R25.2
LED_PWR_STATUS_YEL_R: length 3.2
  BOTTOM w0.203: R25.1 v1(25.53,33.11) 25.53,32.98 26.44,32.06 U4.4
LED_SYNC_STATUS_GRN: length 13.4
  BOTTOM w0.203: LD2.1 7.42,48.42 10.19,45.65 C41.1 R12.2
LED_SYNC_STATUS_GRN_R: length 3.4
  BOTTOM w0.203: U2.3 14.31,41.29 13.34,42.26 v1(13.34,42.5) R12.1
LED_SYNC_STATUS_YEL: length 16.4
  BOTTOM w0.203: R14.2 C44.1 14.25,45.65 13.97,45.93 13.97,46.56 13.33,47.2 10.41,47.2 7.45,50.17 LD2.3
LED_SYNC_STATUS_YEL_R: length 3.1
  BOTTOM w0.203: U2.4 14.96,42.15 v1(14.61,42.5) R14.1
LED_SYS_STAT_CLR_N: length 19.3
  TOP w0.508: v2(42.8,39.01) 40.49,41.32 40.49,43.93 38.51,45.9 v2(34.04,45.9)
  BOTTOM w0.508: U1.11 v2(34.04,45.9) ; v2(42.8,39.01) R4.2 J1.3
LED_SYS_STAT_SCL: length 38.6
  TOP w0.508: v2(31.24,37.2) 36.09,32.34 54,32.34 v2(57.3,35.65)
  BOTTOM w0.508: R8.2 v2(57.3,35.65) ; v2(31.24,37.2) 27.74,40.7 U1.2
LED_SYS_STAT_SCL_R: length 3.8
  BOTTOM w0.508: R8.1 v1(55.24,39.01) J1.4
LED_SYS_STAT_SDA: length 54.8
  TOP w0.508: v2(13.72,38.44) 32.69,38.44 37.52,33.61 53.21,33.61 56.01,36.41 56.01,39.58 v2(54.58,41.01)
  BOTTOM w0.508: J1.6 v2(54.58,41.01) ; v2(13.72,38.44) 13.66,38.5 U2.2
LED_SYS_STAT_SDA_PU0: length 3.4
  BOTTOM w0.203: R13.1 v1(12.06,42.38) 13.01,41.43 U2.1
LED_SYS_STAT_SDA_PU1: length 2.8
  BOTTOM w0.203: U4.1 25.71,30.11 v1(25.53,29.93) R24.1
LED_SYS_STATUS_GRN: length 23.4
  BOTTOM w0.203: R21.2 C48.1 14.18,29.96 13.72,29.49 13.72,29.05 12.95,28.28 10.79,28.28 8.19,30.88 8.19,34.69 5.33,37.55 5.33,40.6 4.51,41.42 LD3.1
LED_SYS_STATUS_GRN_R: length 3.1
  BOTTOM w0.203: U2.12 14.31,32.89 v1(14.35,32.85) R21.1
LED_SYS_STATUS_YEL: length 22.3
  BOTTOM w0.203: LD3.3 4.67,43.17 6.86,40.98 6.86,38.31 9.78,35.39 9.78,30.82 10.95,29.65 12.04,29.65 12.34,29.96 C50.1 R22.2
LED_SYS_STATUS_YEL_R: length 18.9
  TOP w0.203: v2(24.77,30.76) 24.71,30.82 21.46,30.82 18.67,33.61 13.84,33.61 v2(13.08,32.85)
  BOTTOM w0.203: U2.13 13.66,33.94 13.08,33.36 v2(13.08,32.85) R22.1 ; U4.2 v2(24.77,30.76)
MOD_BTN_N: length 42.2
  BOTTOM w0.203: R48.2 20.19,64.81 26.43,58.57 40.83,58.57 44.83,54.57 44.83,48.52 46.35,47.01 J1.11
RST_CP2104: length 5.9
  BOTTOM w0.203: R65.2 Q1.3 37.1,24.03 v1(37.1,23.96) Q2.1
RST_CP2104_N: length 11.1
  BOTTOM w0.203: U3.9 33.91,18.75 v1(35.31,20.15) 35.66,20.51 Q2.3 38.06,20.51 C57.2 R66.2 43.51,20.51 Q4.3
RST_SW_BTN_EN_N: length 9.4
  BOTTOM w0.203: R49.2 v1(9.91,64.6) 8.94,65.57 SW1.4 SW1.1
RST_SW_TO_CP2104: length 28.3
  BOTTOM w0.203: Q4.1 R74.2 46.96,24.5 41.53,29.93 41.53,39.46 43.08,41.01 J1.5
UART_CP2104_RXD: length 3.4
  BOTTOM w0.203: U3.20 34.91,13.31 35.43,12.79 R11.2 R35.2
UART_CP2104_TXD: length 6.5
  TOP w0.203: v2(34.41,12.74) 37.21,12.74 v2(37.46,12.99)
  BOTTOM w0.203: R15.2 v2(37.46,12.99) ; U3.21 34.41,12.74 v2(34.41,12.74) R34.2
USB_CONS_PRSNT_GPIO_N: length 2.9
  BOTTOM w0.203: U3.14 37.19,16.79 v1(37.59,17.18) 37.84,17.43 R55.1
USB_CONS_PRSNT_N: length 51.1
  BOTTOM w0.203: J1.9 50.2,45.01 51.18,44.03 55.5,44.03 58.67,40.85 58.67,25.87 51.31,18.5 42.26,18.5 R64.2 R63.2 C49.1 R55.2
USB_DN: length 25.3
  TOP w0.457: v2(21.01,15.49) 19.9,14.39 18.24,14.39 15.74,11.89 15.74,11.34 v2(15.47,11.07)
  BOTTOM w0.457: v2(21.01,15.49) D19.4 21.77,15.08 22.43,14.42 24.24,14.42 24.35,14.53 L1.4 25.7,14.53 R32.1 ; v2(15.47,11.07) 15.74,11.34 15.74,11.62 15.28,12.07 11.19,12.07 8.94,14.32 8.94,15.21 7.69,16.47 J2.2
USB_DP: length 25.4
  TOP w0.457: v2(16.59,11.07) 16.32,11.34 16.32,11.64 18.48,13.8 19.98,13.8 v2(21.01,12.77)
  BOTTOM w0.457: J2.3 7.86,17.12 9.53,15.45 9.53,14.56 11.43,12.66 15.52,12.66 16.32,11.86 16.32,11.34 v2(16.59,11.07) ; R33.1 25.7,13.73 L1.3 24.35,13.73 24.24,13.84 22.3,13.84 21.77,13.31 D19.3 v2(21.01,12.77)
USB_UART0_RXD: length 62.2
  BOTTOM w0.203: R35.1 R15.1 39.45,11.06 41.15,9.36 48.51,9.36 61.98,22.82 61.98,41.78 56.74,47.01 J1.12
USB_UART0_TXD: length 58.8
  TOP w0.203: v2(35.43,10.25) 40.14,10.25 41.02,11.14 v2(41.15,11.14)
  BOTTOM w0.203: R34.1 R11.1 v2(35.43,10.25) ; J1.10 56.68,45.01 60.33,41.36 60.33,24.3 47.16,11.14 v2(41.15,11.14)
USB_UART_DN: length 6.4
  BOTTOM w0.356: U3.4 30.88,16.29 30.81,16.22 30.73,16.22
  BOTTOM w0.457: 30.73,16.22 30.04,15.52 28.94,14.42 28.19,14.42 28.08,14.53 L1.1 26.73,14.53 R32.2
USB_UART_DP: length 6.5
  BOTTOM w0.356: U3.3 31.13,15.79 30.96,15.61
  BOTTOM w0.457: R33.2 26.73,13.73 L1.2 28.08,13.73 28.19,13.84 29.19,13.84 30.96,15.61
N292646: length 2.6
  BOTTOM w0.203: U3.16 v1(37.59,15.79) 38.7,15.79 C17.1
N535645: length 2
  BOTTOM w0.203: TP1.1 37.47,14.39 36.57,15.29 36.11,15.29 U3.17
N535677: length 2.3
  BOTTOM w0.203: U3.11 34.91,18.57 35.68,19.34 TP2.1

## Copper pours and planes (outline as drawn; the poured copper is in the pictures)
GND on TOP (solid shape): outline of 234 points within 56.29,59 63.29,66
GND on TOP (solid shape): outline of 234 points within 56.29,2.35 63.29,9.35
GND on BOTTOM (solid shape): outline of 234 points within 56.29,59 63.29,66
GND on BOTTOM (solid shape): outline of 234 points within 56.29,2.35 63.29,9.35
GND on TOP: 6.61,20.57 6.27,21.37 5.47,21.7 0.64,21.7 0.64,60.54 1.83,60.54 1.83,66.31 0.64,66.31 0.64,66.92 1.03,67.89 2,68.29 65.9,68.29 66.87,67.89 67.27,66.92 67.27,2 66.87,1.03 65.9,0.64 38.54,0.64 37.57,1.03 37.17,2 37.17,5.92 36.7,7.08 35.54,7.56 2,7.56 1.03,7.96 0.64,8.92 0.64,12.53 5.47,12.53 6.27,12.86 6.61,13.67 ; 3 cut-outs
GND on BOTTOM: 6.61,20.57 6.27,21.37 5.47,21.7 0.64,21.7 0.64,60.54 1.83,60.54 1.83,66.31 0.64,66.31 0.64,66.92 1.03,67.89 2,68.29 65.9,68.29 66.87,67.89 67.27,66.92 67.27,2 66.87,1.03 65.9,0.64 38.54,0.64 37.57,1.03 37.17,2 37.17,5.92 36.7,7.08 35.54,7.56 2,7.56 1.03,7.96 0.64,8.92 0.64,12.53 5.47,12.53 6.27,12.86 6.61,13.67 ; 13 cut-outs
P3V3 on BOTTOM (solid shape): 42.93,46.89 42.93,44.47 42.8,44.35 41.08,44.35 40.64,44.79 40.64,46.82 40.77,46.95 40.83,46.95 40.87,46.99 41.43,46.99 41.43,47.01 42.8,47.01
P3V3 on TOP: 42.89,50.67 38.16,55.39 27.24,55.39 18.54,64.09 10.79,64.09 3.81,57.11 3.81,24.72 4.25,24.28 25.08,24.28 25.34,24.53 25.34,28.53 24.57,29.3 21.46,29.3 17.78,32.98 13.46,32.98 13.34,33.11 13.34,38.57 13.59,38.82 17.14,38.82 18.67,40.35 18.67,46.31 20.45,48.09 37.08,48.09 39.66,45.51 42.68,45.51 42.89,45.72 ; 1 cut-out
P3V3_CP2104 on BOTTOM (solid shape): 32.51,17.81 32.51,17.61 32.63,17.49 32.63,16.68 31.61,16.68 30.47,17.82 30.47,18.96 30.6,19.09 31.24,19.09
P3V3_IN on BOTTOM (solid shape): 42.96,43.65 43.52,43.65 43.52,43.65 47.94,43.65 48.2,43.39 48.2,42.38 47.69,41.87 42.27,41.87 41.91,42.22 41.91,43.65 42.96,43.65
P5V on BOTTOM (solid shape): 7.73,15.75 7.73,14.81 7.43,14.5 6.54,14.5 6.24,14.81 6.24,15.85 6.29,15.9 7.58,15.9
Net_40 on BOTTOM (solid shape): outline of 195 points within 24.23,61.15 28.35,65.26
Net_41 on TOP (solid shape): outline of 195 points within 24.23,61.15 28.35,65.26
Net_42 on BOTTOM (solid shape): outline of 195 points within 48.49,61.02 52.6,65.14
Net_43 on TOP (solid shape): outline of 195 points within 48.49,61.02 52.6,65.14
Net_44 on BOTTOM (solid shape): outline of 195 points within 61.44,11.49 65.56,15.61
Net_45 on TOP (solid shape): outline of 195 points within 61.44,11.49 65.56,15.61

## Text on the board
User.Comments: CR_UNNAMED_1
Ref Des/Silkscreen Top: 95.2227T00 00GP | LABLE 25.4X9.5
PAGE_OUTLINE: 2018.02.06 | UNLESS OTHERWISE SPECIFIED | DIMENSIONS ARE IN INCHES | TOLERANCES ON; | 2 PL DECIMALS +/- .010 | 3 PL DECIMALS +/- .005 | ANGLES +/- 5 | FRACTIONS + | ISSUED | CAD | ENGRG | SIGNATURES | MARS | JENNA | DATE | SCALE | SIZE | FSCM NO | DWG NO | SHEET | REV | DESCRIPTION | REVISIONS | APPROVED | 95.2227T00 | D | C | B | A | 7 | 6 | 5 | 4 | 3 | 2 | 1 | U | f | i | Space
BODY_CENTER: 10.ALL COPPER FEATURES ON THE BOARD ARE TO BE FINISHED WITH OSP COAT.         . | 11.THIS IS A 2 LAYER BOARD. VENDER TO PROVIDE BOARD STACK-UP FOR IMPEDANCE | APPROVAL PRIOR TO BOARD FABRICATION.STACK-UP AND IMPEDANCE TO INCLUDE COPPER | PLANTING THICKNESS ON OUTER LAYERS. | 12.ADD SQUARE SHAPED THIEVING PADS IN 50MILSX50MILS DIMENSION ON ALL THE SIGNAL | 13.NO THIEVING PERMITTED ON ANY ELECTRICAL LAYERS IN THIS AREA. | 14.PCB VENDOR MUST BE UL QUALIFIED | 15.BOARD MUST BE IDENTIFIED WITH APPROPRIATE VENDOR UL IDENTIFACTION MARK,DATE CODE. | OVER BARE COPPER PRIOR TO ANY PLATING FINISH PROCESSES | 2. ALL FINISHED BOARDS TO BE ELECTRICALLY TESTED. | 3. SILKSCREEN TO BE WHITE. NON-CONDUCTIVE , EPOXY INK OR EQUIVALENT. | 4. SOLDERMASK GREEN LIQUID PHOTO-IMAGABLE SMOBC SOLDERMASK TO BE APPLIED | 5. BOARD THICKNESS IS 0.06311" +/- 10% | 6 .NON-FUNCTIONAL PADS ON INTERNAL LAYERS MAY BE OMITTED. | 7 .TEARDROP TRACE ENTRY TO VIAS ON INTERNAL LAYERS, PROVIDED DRC RULES ARE MET. | 8 .ACCEPTABLE MINIMUM ANNULAR RING FOR VIA IS 0.001". | 9 .THIS IS A CONTROLLED IMPEDANCE BOARD. CONTROLS ARE AS FOLLOWS: | 16.PCB MATERIAL UL FLAMMABILITY RATING(94V-0 MINIMUM) | 1. MATERIAL:FR-4 OR EQUIVALENT. THE USE OF SINGLE PLY CONSTRUCION IS OPTIONAL | NOTES: (UNLESS OTHERWISE SPECIFIED) | LAYERS. THESE SHOULD BE 200 MILS AWAY FROM ALL FUNCTIONAL COPPER. DO NOT ADD | THIEVING ON PLANE LAYERS. | IMPEDANCE SHALL BE 50 OHMS +/-10% ON ALL 0.008 INCH TRACES. | IMPEDANCE SHALL BE 90 OHMS +/-10% ON ALL DIFFENTIAL PAIRS WITH 18MIL/5MIL WIDTH/SPACING
User.12: TOP SIDE SOLDER PAST | 1     2
User.13: BOTTM SIDE SOLDER PAST | 2     2
User.14: TOP SIDE SILK SCREEN | 5     6
User.15: BOTTOM SIDE SILK SCREEN | 6     6
User.16: TOP SIDE SOLDERMASK | 3     6
User.17: BOTTOM SIDE SOLDERMASK | 4     6
User.18: : 1 TO 1 | FABRICATION
User.19: : 1 TO 2 | ASSY_TOP | TOP SIDE VIEW
User.20: : 2 TO 2 | ASSY-BOT | BOTTOM SIDE VIEW
User.21: 0.06311 | +/-10% | FOIL - 1.0 OZ. | CORE - 0.05785 | NOTE: COPPER THICKNESS IS INCLUDED IN THE OVER ALL | BOARD THICKNESS SPECIFICATION | COMPONENT SIDE -LAYER1 | SOLDER SIDE    -LAYER2
User.22: COMPONENT SIDE  LAYER1 | 1     6
User.23: BOTTOM SIDE     LAYER2 | 2     6
User.24: 2018/02/06 | PROJECT | P/N:307.01882.005 | LAYER | REV.005 | CAD | H/W | SIGNATURES | SHEET    OF | Mars | Jenna | DATA | 95.2227T00 | GERBER | U | f | i | Space
User.25: TOP SIDE SOLDER PAST & SILK | 1     2
User.26: BOTTOM SIDE SOLDER PAST & SILK | 2     2
User.27: SHEET | DWG NO | FSCM NO | SIZE | SCALE | DATE | 02.06.18 | JENNA | MARS | SIGNATURES | CAD | ENGRG | ISSUED | UNLESS OTHERWISE SPECIFIED | DIMENSIONS ARE IN INCHES | TOLERANCES ON; | 2 PL DECIMALS +/- .010 | 3 PL DECIMALS +/- .005 | ANGLES +/- 5 | FRACTIONS + | APPROVED | REVISIONS | DESCRIPTION | REV | D | 95.2227T00 | B | C | A | 1 | 2 | 3 | 4 | 5 | 6 | 7 | Space | i | f | U
User.32: FIGURE | FHS | 8.0 | 20.0 | 177.0 | 45.0 | 118.0 | 45.0x24.0 | 68.0x24.0 | DRILL CHART: TOP to BOTTOM | ALL UNITS ARE IN MILS | TOLERANCE | +2.0/-5.0 | +3.0/-3.0 | +2.0/-2.0 | +4.0/-4.0 | PLATED | NON-PLATED | QTY | 281 | 16 | 2
